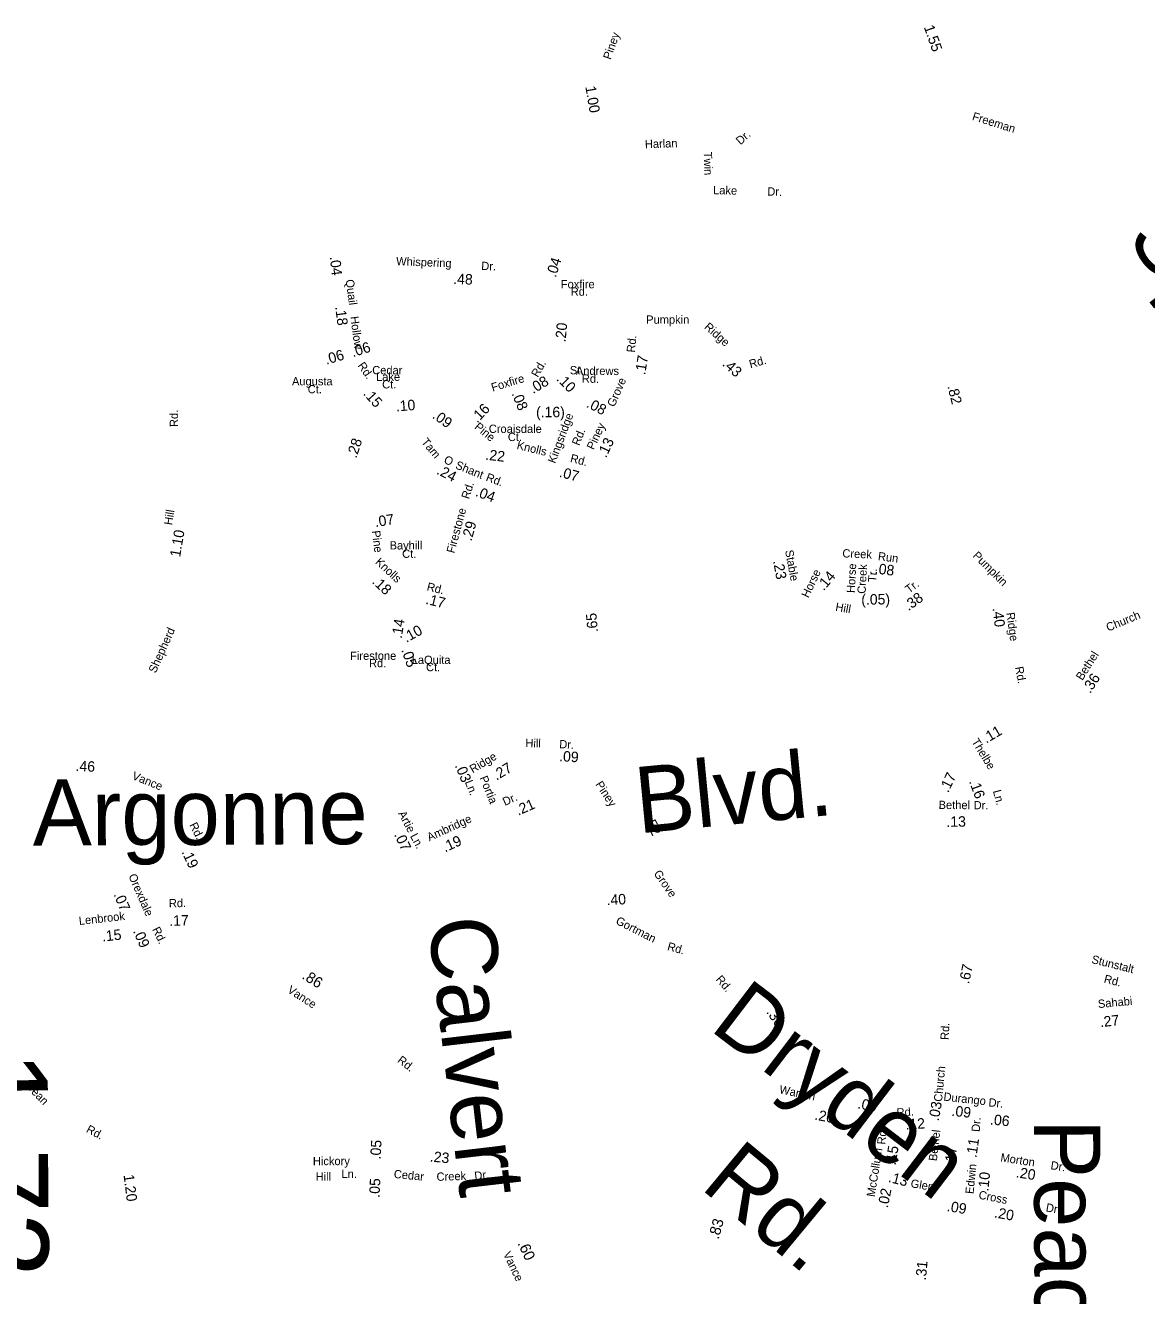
# Model space of a CAD drawing. Extents: x 1553981 to 1780076, y 812965 to 996873.
# Drawn here: x 1639513 to 1641120, y 850888 to 852709 of the extents above; entities that cross this region are included whole.
import ezdxf

# ---------------------------------------------------------------- set-up
doc = ezdxf.new("R2010")
doc.units = 0
for name, color, linetype in [('Exist Road Non-System Type 51 Label', 7, 'Continuous'), ('Exist Road Secondary Mileage Hundredths English Label', 7, 'Continuous'), ('Map Preparation Border Antique Large Shape', 7, 'Continuous')]:
    doc.layers.add(name, color=color, linetype=linetype)

msp = doc.modelspace()

# ---------------------------------------------------------------- texts
at = {"layer": 'Exist Road Non-System Type 51 Label'}
for s, height, rotation, p in [('Harlan', 11.87, 1.7557, (1640400.8, 852532.9)), ('Dr.', 11.88, 42.1108, (1640537.6, 852537)), ('Twin', 11.87, 271.555, (1640485, 852527.6)), ('Lake', 11.87, 358.5206, (1640498.3, 852467.1)), ('Dr.', 11.87, 358.5206, (1640576, 852465.1)), ('Springwood', 95, 307.8109, (1641089.3, 852403.1)), ('Blvd.', 95, 5.4849, (1640391.3, 851550.3)), ('Argonne', 95, 0.2852, (1639523.3, 851532.8)), ('Calvert', 95, 276.6658, (1640089.4, 851426.2)), ('Stunstalt', 11.87, 346.1236, (1641040, 851364.7)), ('Rd.', 11.87, 346.1236, (1641057.8, 851336.7)), ('Dryden', 95, 322.6881, (1640491.7, 851269.7)), ('Peachtree', 95, 270.1933, (1640958.4, 851140.8)), ('Rd.', 95, 320.361, (1640478.6, 851042.3))]:
    msp.add_text(s, height=height, rotation=rotation, dxfattribs=at).set_placement(p)
at = {"layer": 'Exist Road Secondary Mileage Hundredths English Label'}
for s, height, rotation, p in [('1.55', 15, 289.279, (1640800.3, 852706.7)), ('1.00', 15, 279.6408, (1640315.2, 852621.1)), ('.04', 15, 276.5196, (1639948.9, 852377.3)), ('.04', 15, 72.3282, (1640272.8, 852346.7)), ('.48', 15, 357.861, (1640125.7, 852338.3)), ('.18', 15, 277.4904, (1639956.6, 852305.5)), ('.20', 15, 84.783, (1640286.9, 852254.3)), ('.06', 15, 17.2822, (1639982.2, 852233.2)), ('.06', 15, 16.5374, (1639944.1, 852222.4)), ('.17', 15, 80.9118, (1640401, 852207.1)), ('.43', 15, 317.8043, (1640510.6, 852222.2)), ('.08', 15, 31.0886, (1640240.4, 852180.3)), ('.10', 15, 315.0857, (1640272.8, 852201.1)), ('.15', 15, 311.9127, (1639996, 852180.4)), ('.82', 15, 284.0667, (1640834.1, 852191.5)), ('.10', 15, 4.7797, (1640044.3, 852155.4)), ('.16', 15, 46.1425, (1640160.3, 852138)), ('.08', 15, 292.203, (1640209.3, 852181.1)), ('.08', 15, 333.0726, (1640315.7, 852162.3)), ('.09', 15, 324.0277, (1640094.9, 852147)), ('(.16)', 15, 359.6997, (1640244.6, 852147.3)), ('.28', 15, 71.9981, (1639987.1, 852087.6)), ('.13', 15, 64.6185, (1640345, 852088.1)), ('.22', 15, 353.5164, (1640171.5, 852086.4)), ('.24', 15, 333.054, (1640100.9, 852066.5)), ('.07', 15, 345.4047, (1640276.9, 852061.9)), ('.04', 15, 339.5375, (1640156.6, 852034.6)), ('.07', 15, 8.6964, (1640014.6, 851989.7)), ('1.10', 15, 80.3634, (1639734.4, 851945.9)), ('.29', 15, 74.3555, (1640152, 851968.8)), ('.23', 15, 280.404, (1640584.3, 851941)), ('.08', 15, 352.7867, (1640729.5, 851923.3)), ('.18', 15, 317.214, (1640008.5, 851910.1)), ('.14', 15, 50.0316, (1640657, 851897.4)), ('.17', 15, 346.2737, (1640085.5, 851879.8)), ('(.05)', 15, 0.6392, (1640710.9, 851878.4)), ('.38', 15, 35.7688, (1640778.4, 851868.9)), ('.14', 15, 80.7967, (1640052, 851829.3)), ('.65', 15, 95.2857, (1640333.5, 851839.4)), ('.40', 15, 276.5668, (1640899, 851873.3)), ('.10', 15, 28.7565, (1640058.8, 851823.7)), ('.05', 15, 289.0907, (1640051.3, 851813.5)), ('.36', 15, 57.5896, (1641039, 851750.2)), ('.11', 15, 30.4295, (1640889.9, 851679.1)), ('.46', 15, 357.3552, (1639584.3, 851640)), ('.09', 15, 356.3902, (1640277.4, 851654.1)), ('.03', 15, 292.311, (1640128, 851647.8)), ('.27', 15, 30.7405, (1640187.9, 851626)), ('.17', 15, 64.0144, (1640835.3, 851608)), ('.16', 15, 290.2818, (1640865.1, 851624.9)), ('.21', 15, 23.8705, (1640219.1, 851575.7)), ('.52', 15, 297.3708, (1640399.1, 851570.4)), ('.13', 15, 0.7647, (1640833, 851559.8)), ('.07', 15, 295.5283, (1640040.8, 851548.8)), ('.19', 15, 24.5877, (1640114.2, 851523.1)), ('.19', 15, 295.1742, (1639736.1, 851524)), ('.07', 15, 293.45, (1639638.7, 851462.9)), ('.40', 15, 3.048, (1640346.1, 851447.5)), ('.17', 15, 1.2145, (1639719, 851417.9)), ('.15', 15, 6.3312, (1639623.3, 851395.3)), ('.09', 15, 293.4427, (1639666.7, 851410.4)), ('.67', 15, 78.3431, (1640865.2, 851333.9)), ('.86', 15.62, 328.0585, (1639908, 851343)), ('.36', 15, 303.0944, (1640574.2, 851294.4)), ('.27', 15, 6.548, (1641053.6, 851272.5)), ('1.73', 125, 270.2413, (1639419.6, 851238.3)), ('.09', 15, 349.5659, (1640704.7, 851156.4)), ('.03', 15, 80.2961, (1640821.8, 851137.4)), ('.20', 15, 349.3956, (1640643.1, 851140.2)), ('.09', 15, 353.6295, (1640839.6, 851145.7)), ('.06', 15, 354.305, (1640894.9, 851133.2)), ('.12', 15, 3.5273, (1640774.7, 851125.8)), ('.05', 15, 86.9375, (1640021.8, 851082.8)), ('.11', 15, 81.4935, (1640875.7, 851084.8)), ('.23', 15, 354.5023, (1640091.9, 851080.1)), ('.15', 15, 80.9006, (1640760, 851073.9)), ('.17', 15, 84.6489, (1640845.3, 851073.5)), ('.20', 15, 351.2945, (1640931.8, 851057.5)), ('1.20', 15, 277.2674, (1639653.3, 851060.7)), ('.05', 15, 87.405, (1640020.3, 851027.9)), ('.13', 15, 345.7884, (1640748.5, 851051)), ('.10', 15, 84.5448, (1640892.9, 851036.6)), ('.02', 15, 78.5695, (1640748.7, 851012.7)), ('.09', 15, 350.2788, (1640832.8, 851009.2)), ('.83', 15.62, 74.8632, (1640506.4, 850967.7)), ('.20', 15, 349.792, (1640900.7, 851000)), ('.60', 15.62, 295.3014, (1640217.7, 850962.7)), ('.31', 15, 84.7821, (1640803.4, 850909.3))]:
    msp.add_text(s, height=height, rotation=rotation, dxfattribs=at).set_placement(p)
at = {"layer": 'Map Preparation Border Antique Large Shape'}
for s, height, rotation, p in [('Piney', 11.87, 70.4761, (1640351.5, 852659.1)), ('Freeman', 11.87, 342.5091, (1640868.9, 852573.7)), ('Whispering', 11.88, 357.732, (1640043.9, 852365.2)), ('Dr.', 11.88, 357.861, (1640165.9, 852358.4)), ('Quail', 11.88, 277.4904, (1639971.7, 852344.1)), ('Hollow', 11.87, 277.4825, (1639978.4, 852291.3)), ('Pumpkin', 11.87, 0.1898, (1640402.5, 852281.2)), ('Ridge', 11.88, 318.2855, (1640484.8, 852275.3)), ('Rd.', 11.88, 84.2614, (1640386.1, 852239.6)), ('Rd.', 11.88, 304.8616, (1639988.4, 852221.2)), ('Rd.', 11.87, 60.1103, (1640247.2, 852203.5)), ('St.', 11.88, 359.4499, (1640293, 852208.8)), ('Andrews', 11.88, 359.6762, (1640301.7, 852208)), ('Rd.', 11.88, 15.5096, (1640551.9, 852217.4)), ('Foxfire', 11.88, 16.8612, (1640182.4, 852183.9)), ('Rd.', 11.88, 359.5207, (1640310.2, 852196.7)), ('Grove', 11.87, 66.5111, (1640356.9, 852161)), ('Rd.', 11.88, 90.634, (1639731.5, 852133.2)), ('Kingsridge', 11.88, 69.4571, (1640272.1, 852080.1)), ('Pine', 11.88, 320.1728, (1640155.4, 852131.8)), ('Rd.', 11.88, 67.7942, (1640306.4, 852105.6)), ('Piney', 11.88, 64.7015, (1640327.3, 852099.6)), ('Tam', 11.87, 309.6472, (1640079.5, 852111.4)), ('Knolls', 11.88, 346.564, (1640216.2, 852101.8)), ('O', 11.9, 335.1811, (1640111.4, 852082.2)), ('Rd.', 11.87, 345.4047, (1640292.8, 852083.3)), ('Shant', 11.87, 337.7511, (1640128, 852074.2)), ('Rd.', 11.88, 339.5375, (1640171.8, 852056.5)), ('Rd.', 11.88, 71.7737, (1640148.4, 852029)), ('Hill', 11.87, 80.7512, (1639722.9, 851991.9)), ('Firestone', 11.87, 74.8386, (1640127.4, 851951.4)), ('Pine', 11.87, 277.0677, (1640009.2, 851984.1)), ('Knolls', 11.88, 316.9534, (1640013.3, 851938.4)), ('Stable', 11.88, 280.404, (1640601.5, 851955.8)), ('Creek', 11.87, 357.6542, (1640683.5, 851946.3)), ('Run', 11.87, 352.7867, (1640734.2, 851942.3)), ('Pumpkin', 11.88, 315.1904, (1640869.7, 851947.7)), ('Horse', 11.88, 64.732, (1640635.1, 851887.3)), ('Horse', 11.88, 87.1294, (1640701.5, 851895)), ('Creek', 11.88, 87.1294, (1640717, 851893.8)), ('Tr.', 11.88, 87.1294, (1640732.3, 851910.7)), ('Rd.', 11.87, 346.4325, (1640087.3, 851899.1)), ('Tr.', 11.87, 37.1756, (1640779.4, 851894.1)), ('Hill', 11.87, 350.1213, (1640673.1, 851869.8)), ('Ridge', 11.88, 277.8316, (1640918.7, 851866.6)), ('Church', 11.88, 22.5975, (1641064.8, 851839.7)), ('Shepherd', 11.88, 65.9523, (1639699.4, 851779.4)), ('Bethel', 11.88, 57.548, (1641027.6, 851768.9)), ('Rd.', 11.88, 280.6412, (1640931.1, 851788.7)), ('Hill', 11.87, 358.6986, (1640229.3, 851674.3)), ('Dr.', 11.87, 356.3902, (1640277.6, 851672.8)), ('Thelbe', 11.88, 301.2763, (1640868.4, 851682.2)), ('Ridge', 11.88, 30.7405, (1640153.8, 851636.4)), ('Vance', 11.87, 338.2444, (1639664.6, 851628.5)), ('Ln.', 11.88, 291.7486, (1640142.3, 851624.2)), ('Portia', 11.88, 291.7486, (1640163.5, 851630.3)), ('Piney', 11.88, 303.3076, (1640329.2, 851620.7)), ('Dr.', 11.88, 23.8705, (1640199.9, 851589.8)), ('Ln.', 11.88, 284.8805, (1640899.4, 851611.3)), ('Bethel', 11.87, 359.5793, (1640821.6, 851585.5)), ('Dr.', 11.88, 359.4035, (1640871.8, 851585.1)), ('Rd.', 11.87, 296.4439, (1639747.4, 851562.7)), ('Artie', 11.88, 298.0305, (1640046.5, 851579)), ('Ambridge', 11.88, 24.7446, (1640091.7, 851538.9)), ('Ln.', 11.88, 298.0305, (1640063.7, 851546.7)), ('Orexdale', 11.88, 293.45, (1639660.1, 851489.6)), ('Grove', 11.88, 304.88, (1640412.7, 851492.8)), ('Rd.', 11.88, 0.9841, (1639718.4, 851444.5)), ('Lenbrook', 11.88, 6.3312, (1639589.9, 851419.1)), ('Rd.', 11.87, 295.7299, (1639694.1, 851413)), ('Gortman', 11.87, 332.9546, (1640357.8, 851421.4)), ('Rd.', 11.88, 344.6464, (1640431.9, 851383.4)), ('Rd.', 11.87, 310.9684, (1640501.5, 851340.7)), ('Vance', 11.88, 327.1313, (1639887.2, 851323.3)), ('Sahabi', 11.88, 5.3034, (1641050.5, 851300)), ('Rd.', 11.88, 87.0693, (1640836, 851254.1)), ('Rd.', 11.88, 322.2328, (1640044.9, 851223.3)), ('Church', 11.88, 84.6443, (1640826.5, 851165.3)), ('Dean', 11.88, 314.6009, (1639512.1, 851187.1)), ('Warren', 11.88, 348.2766, (1640592.6, 851178)), ('Durango', 11.87, 353.6295, (1640828.2, 851167.5)), ('Dr.', 11.88, 354.305, (1640892.7, 851159.2)), ('Rd.', 11.88, 3.5273, (1640761.8, 851144.3)), ('Rd.', 11.88, 331.8506, (1639598.8, 851122.7)), ('Rd.', 11.88, 84.7348, (1640745.2, 851104)), ('Dr.', 11.88, 85.3587, (1640880.5, 851122.1)), ('Bethel', 11.88, 83.5469, (1640819.1, 851080.2)), ('McCollum', 11.88, 80.9006, (1640730, 851028.7)), ('Morton', 11.88, 351.2945, (1640909.8, 851080.3)), ('Edwin', 11.87, 84.5448, (1640871.7, 851033.1)), ('Dr.', 11.88, 351.2165, (1640981.6, 851069.1)), ('Cedar', 11.87, 354.612, (1640040.3, 851056.5)), ('Creek', 11.88, 2.0082, (1640102.2, 851052.2)), ('Dr.', 11.87, 7.3725, (1640157, 851053.3)), ('Glen', 11.88, 350.2788, (1640780.9, 851043.3)), ('Cross', 11.88, 349.1017, (1640878.3, 851026.9)), ('Dr.', 11.88, 349.792, (1640974.7, 851008.7)), ('Vance', 11.88, 295.4012, (1640197.1, 850947.5))]:
    msp.add_text(s, height=height, rotation=rotation, dxfattribs=at).set_placement(p)
for s, p in [('Foxfire', (1640280.1, 852332.1)), ('Rd.', (1640294.3, 852321.4)), ('Cedar', (1640009.8, 852208.8)), ('Augusta', (1639894.8, 852192.9)), ('Lake', (1640015.3, 852199.3)), ('Ct.', (1640024, 852188.5)), ('Ct.', (1639917.3, 852181.5)), ('Croaisdale', (1640176.9, 852124.7)), ('Ct.', (1640204.2, 852113)), ('Bayhill', (1640034.7, 851957.6)), ('Ct.', (1640052.7, 851945.6)), ('Firestone', (1639978.1, 851799.3)), ('Rd.', (1640005.2, 851788.8)), ('LaQuita', (1640066.4, 851793.4)), ('Ct.', (1640086.9, 851783.1)), ('Hickory', (1639924.8, 851074.8)), ('Hill', (1639928.7, 851052.5)), ('Ln.', (1639965.8, 851056.3))]:
    msp.add_text(s, height=11.88, dxfattribs=at).set_placement(p)

doc.saveas('drawing.dxf')
